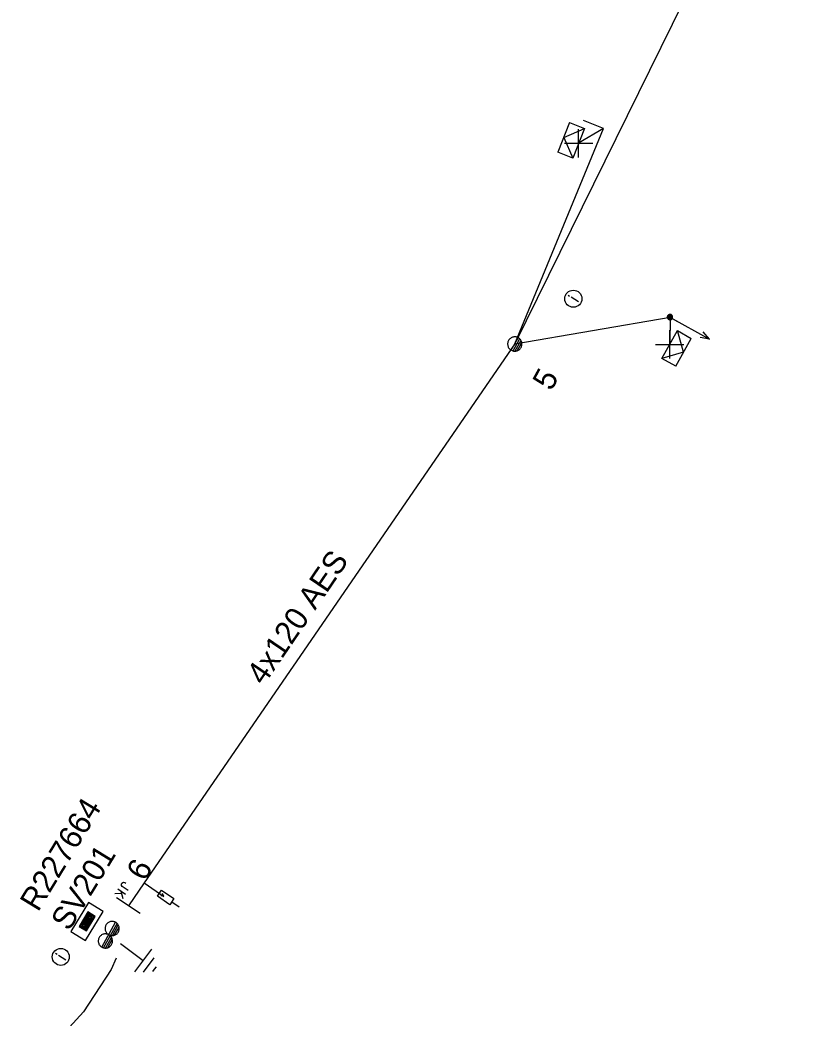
# Model space of a CAD drawing. Extents: x -544780 to -541582, y -1198995 to -1196551.
# Drawn here: x -543891.68 to -543856.56, y -1197432.33 to -1197388.43 of the extents above; entities that cross this region are included whole.
import ezdxf

# ---------------------------------------------------------------- set-up
doc = ezdxf.new("R2010")
doc.units = 0
for name, color, linetype in [('Vrstva 1', 7, 'Continuous'), ('Vrstva 10', 7, 'Continuous'), ('Vrstva 13', 7, 'Continuous'), ('Vrstva 14', 7, 'Continuous'), ('Vrstva 15', 7, 'Continuous'), ('Vrstva 16', 7, 'Continuous'), ('Vrstva 18', 7, 'Continuous'), ('Vrstva 2', 7, 'Continuous'), ('Vrstva 28', 7, 'Continuous'), ('Vrstva 29', 7, 'Continuous'), ('Vrstva 30', 7, 'Continuous'), ('Vrstva 31', 7, 'Continuous'), ('Vrstva 34', 7, 'Continuous'), ('Vrstva 36', 7, 'Continuous'), ('Vrstva 5', 7, 'Continuous'), ('Vrstva 50', 7, 'Continuous'), ('Vrstva 51', 7, 'Continuous'), ('Vrstva 54', 7, 'Continuous'), ('Vrstva 8', 7, 'Continuous'), ('Vrstva 9', 7, 'Continuous')]:
    doc.layers.add(name, color=color, linetype=linetype)

# ---------------------------------------------------------------- blocks, each defined once
blk = doc.blocks.new('NN440')
at = {"layer": 'Vrstva 2'}
for points in [[(0.631, -0.004), (0.627, 0.062), (0.617, 0.127), (0.6, 0.191), (0.577, 0.252), (0.547, 0.311), (0.511, 0.366), (0.469, 0.417), (0.423, 0.464), (0.371, 0.505), (0.316, 0.542), (0.257, 0.571), (0.196, 0.595), (0.132, 0.612), (0.067, 0.622), (0.001, 0.626), (-0.065, 0.622), (-0.13, 0.612), (-0.194, 0.595), (-0.255, 0.571), (-0.314, 0.542), (-0.369, 0.505), (-0.42, 0.464), (-0.467, 0.417), (-0.509, 0.366), (-0.544, 0.311), (-0.574, 0.252), (-0.598, 0.191), (-0.615, 0.127), (-0.626, 0.062), (-0.629, -0.004), (-0.626, -0.07), (-0.615, -0.135), (-0.598, -0.199), (-0.574, -0.26), (-0.544, -0.319), (-0.509, -0.374), (-0.467, -0.426), (-0.42, -0.472), (-0.369, -0.514), (-0.314, -0.55), (-0.255, -0.58), (-0.194, -0.603), (-0.13, -0.62), (-0.065, -0.631), (0.001, -0.634), (0.067, -0.631), (0.132, -0.62), (0.196, -0.603), (0.257, -0.58), (0.316, -0.55), (0.371, -0.514), (0.423, -0.472), (0.469, -0.426), (0.511, -0.374), (0.547, -0.319), (0.577, -0.26), (0.6, -0.199), (0.617, -0.135), (0.627, -0.07), (0.631, -0.004)], [(-0.631, 0), (0.629, 0)], [(-0.601, -0.177), (0.57, -0.177)], [(-0.513, -0.325), (0.501, -0.325)], [(-0.375, -0.473), (0.353, -0.473)]]:
    blk.add_lwpolyline(points, dxfattribs=at)
blk = doc.blocks.new('NN450')
at = {"layer": 'Vrstva 2'}
for points in [[(0, 0), (-0.003, 0.065), (-0.013, 0.13), (-0.031, 0.193), (-0.054, 0.254), (-0.084, 0.312), (-0.119, 0.367), (-0.161, 0.418), (-0.207, 0.464), (-0.258, 0.505), (-0.313, 0.541), (-0.371, 0.571), (-0.432, 0.594), (-0.495, 0.611), (-0.559, 0.621), (-0.625, 0.625), (-0.69, 0.621), (-0.755, 0.611), (-0.818, 0.594), (-0.879, 0.571), (-0.938, 0.541), (-0.992, 0.505), (-1.043, 0.464), (-1.089, 0.418), (-1.13, 0.367), (-1.166, 0.312), (-1.196, 0.254), (-1.219, 0.193), (-1.236, 0.13), (-1.246, 0.065), (-1.25, 0), (-1.246, -0.066), (-1.236, -0.13), (-1.219, -0.193), (-1.196, -0.255), (-1.166, -0.313), (-1.13, -0.368), (-1.089, -0.419), (-1.043, -0.465), (-0.992, -0.506), (-0.937, -0.542), (-0.879, -0.571), (-0.818, -0.595), (-0.755, -0.612), (-0.69, -0.622), (-0.625, -0.625), (-0.559, -0.622), (-0.495, -0.612), (-0.432, -0.595), (-0.37, -0.571), (-0.312, -0.542), (-0.258, -0.506), (-0.207, -0.465), (-0.161, -0.419), (-0.119, -0.368), (-0.084, -0.313), (-0.054, -0.254), (-0.031, -0.193), (-0.013, -0.13), (-0.003, -0.066), (0, 0)], [(1.25, 0), (1.247, 0.065), (1.237, 0.13), (1.219, 0.193), (1.196, 0.254), (1.166, 0.312), (1.131, 0.367), (1.089, 0.418), (1.043, 0.464), (0.992, 0.505), (0.937, 0.541), (0.879, 0.571), (0.818, 0.594), (0.755, 0.611), (0.691, 0.621), (0.625, 0.625), (0.56, 0.621), (0.495, 0.611), (0.432, 0.594), (0.371, 0.571), (0.312, 0.541), (0.258, 0.505), (0.207, 0.464), (0.161, 0.418), (0.12, 0.367), (0.084, 0.312), (0.054, 0.254), (0.031, 0.193), (0.014, 0.13), (0.004, 0.065), (0, 0), (0.004, -0.066), (0.014, -0.13), (0.031, -0.193), (0.054, -0.255), (0.084, -0.313), (0.12, -0.368), (0.161, -0.419), (0.207, -0.465), (0.258, -0.506), (0.313, -0.542), (0.371, -0.571), (0.432, -0.595), (0.495, -0.612), (0.56, -0.622), (0.625, -0.625), (0.691, -0.622), (0.755, -0.612), (0.818, -0.595), (0.88, -0.571), (0.938, -0.542), (0.992, -0.506), (1.043, -0.465), (1.089, -0.419), (1.131, -0.368), (1.166, -0.313), (1.196, -0.254), (1.219, -0.193), (1.237, -0.13), (1.247, -0.066), (1.25, 0)], [(-1.25, 0), (1.25, 0)], [(-1.23, -0.158), (-0.02, -0.158)], [(-1.161, -0.315), (-0.088, -0.315)], [(-1.033, -0.473), (-0.216, -0.473)], [(0.02, -0.158), (1.23, -0.158)], [(0.089, -0.315), (1.162, -0.315)], [(0.217, -0.473), (1.034, -0.473)]]:
    blk.add_lwpolyline(points, dxfattribs=at)
blk = doc.blocks.new('NN560')
at = {"layer": 'Vrstva 2'}
for points in [[(1.999, -0.001), (1.59, 0.141)], [(0, -0.001), (1.999, -0.001)], [(1.999, -0.001), (1.59, -0.134)]]:
    blk.add_lwpolyline(points, dxfattribs=at)
blk = doc.blocks.new('NN840')
at = {"layer": 'Vrstva 15'}
for points in [[(0.003, 0.619), (0.003, -0.631)], [(-0.538, -0.385), (-0.538, -0.71)], [(-0.332, -0.385), (-0.332, -0.798)], [(-0.332, -0.641), (-0.125, -0.385)], [(-0.745, -0.71), (-0.745, -0.66)], [(-0.73, -0.764), (-0.745, -0.71)], [(-0.657, -0.798), (-0.73, -0.764)], [(-0.627, -0.798), (-0.657, -0.798)], [(-0.558, -0.764), (-0.627, -0.798)], [(-0.538, -0.71), (-0.558, -0.764)], [(-0.263, -0.557), (-0.091, -0.798)]]:
    blk.add_lwpolyline(points, dxfattribs=at)
blk = doc.blocks.new('NN770')
at = {"layer": 'Vrstva 10'}
for p, q in [((0.002, 0.187), (0.002, 0.263)), ((0.002, -0.276), (0.002, 0.111))]:
    blk.add_line(p, q, dxfattribs=at)
blk.add_circle((0, -0.008), 0.375, dxfattribs=at)
blk = doc.blocks.new('NN800')
at = {"layer": 'Vrstva 1'}
for points in [[(-0.442, 0.442), (0.442, -0.442)], [(-0.442, -0.442), (0.442, 0.442)]]:
    blk.add_lwpolyline(points, dxfattribs=at)
blk = doc.blocks.new('NN820')
at = {"layer": 'Vrstva 13'}
for points in [[(-0.003, 0.004), (-0.003, -1.049)], [(-0.165, -0.813), (0.165, -0.813)], [(-0.165, -1.473), (-0.165, -0.813)], [(0.165, -0.813), (0.165, -1.473)], [(-0.003, -1.049), (-0.062, -0.926)], [(-0.003, -1.049), (0.057, -0.926)], [(0.165, -1.473), (-0.165, -1.473)], [(-0.003, -1.473), (-0.003, -1.871)]]:
    blk.add_lwpolyline(points, dxfattribs=at)
blk = doc.blocks.new('NN620')
at = {"layer": 'Vrstva 8'}
for points in [[(0.752, 0.004), (-0.748, 0.004)], [(-0.748, 0.004), (-0.748, -0.746)], [(0.752, -0.746), (0.752, 0.004)], [(0.368, -0.18), (-0.376, -0.18)], [(-0.376, -0.18), (-0.376, -0.558)], [(0.321, -0.227), (-0.329, -0.227)], [(-0.329, -0.227), (-0.329, -0.51)], [(0.274, -0.274), (-0.281, -0.274)], [(-0.281, -0.274), (-0.281, -0.463)], [(0.227, -0.321), (-0.234, -0.321)], [(-0.234, -0.321), (-0.234, -0.416)], [(-0.234, -0.416), (0.227, -0.416)], [(-0.193, -0.369), (0.185, -0.369)], [(0.227, -0.416), (0.227, -0.321)], [(0.274, -0.463), (0.274, -0.274)], [(0.321, -0.51), (0.321, -0.227)], [(0.368, -0.558), (0.368, -0.18)], [(-0.748, -0.746), (0.752, -0.746)], [(-0.376, -0.558), (0.368, -0.558)], [(-0.329, -0.51), (0.321, -0.51)], [(-0.281, -0.463), (0.274, -0.463)]]:
    blk.add_lwpolyline(points, dxfattribs=at)
blk = doc.blocks.new('NN630')
at = {"layer": 'Vrstva 9'}
for points in [[(-0.003, -0.7), (-0.703, 0)], [(-0.703, -0.7), (-0.703, 0), (0.697, 0), (0.697, -0.7)], [(-0.003, -0.7), (0.697, 0)], [(-0.703, -0.7), (0.697, -0.7)]]:
    blk.add_lwpolyline(points, dxfattribs=at)
blk = doc.blocks.new('NN810')
at = {"layer": 'Vrstva 14'}
for points in [[(0.004, -0.64), (0.004, -1.89)], [(0.629, -1.89), (-0.621, -1.89)], [(0.388, -2.2), (-0.399, -2.2)], [(0.004, -2.515), (-0.124, -2.515)], [(0.137, -2.515), (0.004, -2.515)]]:
    blk.add_lwpolyline(points, dxfattribs=at)
blk = doc.blocks.new('NN500')
at = {"layer": 'Vrstva 2'}
for points in [[(-0.001, -0.235), (0.023, -0.234), (0.048, -0.23), (0.071, -0.224), (0.094, -0.215), (0.116, -0.204), (0.137, -0.191), (0.156, -0.175), (0.173, -0.158), (0.189, -0.139), (0.202, -0.118), (0.213, -0.096), (0.222, -0.073), (0.229, -0.049), (0.232, -0.025), (0.234, 0), (0.232, 0.024), (0.229, 0.048), (0.222, 0.072), (0.213, 0.095), (0.202, 0.117), (0.189, 0.138), (0.173, 0.157), (0.156, 0.174), (0.137, 0.19), (0.116, 0.203), (0.094, 0.214), (0.071, 0.223), (0.048, 0.229), (0.023, 0.233), (-0.001, 0.235), (-0.026, 0.233), (-0.05, 0.229), (-0.074, 0.223), (-0.097, 0.214), (-0.119, 0.203), (-0.139, 0.19), (-0.158, 0.174), (-0.176, 0.157), (-0.191, 0.138), (-0.205, 0.117), (-0.216, 0.095), (-0.225, 0.072), (-0.231, 0.048), (-0.235, 0.024), (-0.236, 0), (-0.235, -0.025), (-0.231, -0.049), (-0.225, -0.073), (-0.216, -0.096), (-0.205, -0.118), (-0.191, -0.139), (-0.176, -0.158), (-0.158, -0.175), (-0.139, -0.191), (-0.119, -0.204), (-0.097, -0.215), (-0.074, -0.224), (-0.05, -0.23), (-0.026, -0.234), (-0.001, -0.235)], [(-0.001, -0.235), (0.023, -0.234), (0.048, -0.23), (0.071, -0.224), (0.094, -0.215), (0.116, -0.204), (0.137, -0.191), (0.156, -0.175), (0.173, -0.158), (0.189, -0.139), (0.202, -0.118), (0.213, -0.096), (0.222, -0.073), (0.229, -0.049), (0.232, -0.025), (0.234, 0), (0.232, 0.024), (0.229, 0.048), (0.222, 0.072), (0.213, 0.095), (0.202, 0.117), (0.189, 0.138), (0.173, 0.157), (0.156, 0.174), (0.137, 0.19), (0.116, 0.203), (0.094, 0.214), (0.071, 0.223), (0.048, 0.229), (0.023, 0.233), (-0.001, 0.235), (-0.026, 0.233), (-0.05, 0.229), (-0.074, 0.223), (-0.097, 0.214), (-0.119, 0.203), (-0.139, 0.19), (-0.158, 0.174), (-0.176, 0.157), (-0.191, 0.138), (-0.205, 0.117), (-0.216, 0.095), (-0.225, 0.072), (-0.231, 0.048), (-0.235, 0.024), (-0.236, 0), (-0.235, -0.025), (-0.231, -0.049), (-0.225, -0.073), (-0.216, -0.096), (-0.205, -0.118), (-0.191, -0.139), (-0.176, -0.158), (-0.158, -0.175), (-0.139, -0.191), (-0.119, -0.204), (-0.097, -0.215), (-0.074, -0.224), (-0.05, -0.23), (-0.026, -0.234), (-0.001, -0.235)], [(-0.001, -0.206), (0.02, -0.205), (0.041, -0.201), (0.062, -0.196), (0.082, -0.188), (0.101, -0.178), (0.12, -0.167), (0.136, -0.153), (0.151, -0.138), (0.165, -0.121), (0.177, -0.103), (0.186, -0.084), (0.194, -0.064), (0.2, -0.043), (0.203, -0.022), (0.204, 0), (0.203, 0.021), (0.2, 0.042), (0.194, 0.063), (0.186, 0.083), (0.177, 0.102), (0.165, 0.12), (0.151, 0.137), (0.136, 0.152), (0.12, 0.166), (0.101, 0.177), (0.082, 0.187), (0.062, 0.195), (0.041, 0.2), (0.02, 0.204), (-0.001, 0.205), (-0.023, 0.204), (-0.044, 0.2), (-0.065, 0.195), (-0.085, 0.187), (-0.104, 0.177), (-0.122, 0.166), (-0.139, 0.152), (-0.154, 0.137), (-0.167, 0.12), (-0.179, 0.102), (-0.189, 0.083), (-0.197, 0.063), (-0.202, 0.042), (-0.205, 0.021), (-0.207, 0), (-0.205, -0.022), (-0.202, -0.043), (-0.197, -0.064), (-0.189, -0.084), (-0.179, -0.103), (-0.167, -0.121), (-0.154, -0.138), (-0.139, -0.153), (-0.122, -0.167), (-0.104, -0.178), (-0.085, -0.188), (-0.065, -0.196), (-0.044, -0.201), (-0.023, -0.205), (-0.001, -0.206)], [(-0.001, -0.176), (0.017, -0.175), (0.035, -0.172), (0.053, -0.168), (0.07, -0.161), (0.087, -0.153), (0.102, -0.143), (0.116, -0.131), (0.129, -0.118), (0.141, -0.104), (0.151, -0.088), (0.159, -0.072), (0.166, -0.055), (0.171, -0.037), (0.174, -0.019), (0.175, 0), (0.174, 0.018), (0.171, 0.036), (0.166, 0.054), (0.159, 0.071), (0.151, 0.087), (0.141, 0.103), (0.129, 0.117), (0.116, 0.13), (0.102, 0.142), (0.087, 0.152), (0.07, 0.16), (0.053, 0.167), (0.035, 0.172), (0.017, 0.174), (-0.001, 0.175), (-0.02, 0.174), (-0.038, 0.172), (-0.056, 0.167), (-0.073, 0.16), (-0.089, 0.152), (-0.105, 0.142), (-0.119, 0.13), (-0.132, 0.117), (-0.143, 0.103), (-0.153, 0.087), (-0.162, 0.071), (-0.168, 0.054), (-0.173, 0.036), (-0.176, 0.018), (-0.177, 0), (-0.176, -0.019), (-0.173, -0.037), (-0.168, -0.055), (-0.162, -0.072), (-0.153, -0.088), (-0.143, -0.104), (-0.132, -0.118), (-0.119, -0.131), (-0.105, -0.143), (-0.089, -0.153), (-0.073, -0.161), (-0.056, -0.168), (-0.038, -0.172), (-0.02, -0.175), (-0.001, -0.176)], [(-0.001, -0.147), (0.014, -0.146), (0.029, -0.143), (0.044, -0.139), (0.058, -0.134), (0.072, -0.127), (0.085, -0.119), (0.097, -0.109), (0.107, -0.098), (0.117, -0.086), (0.125, -0.073), (0.132, -0.06), (0.138, -0.046), (0.142, -0.031), (0.144, -0.016), (0.145, 0), (0.144, 0.015), (0.142, 0.03), (0.138, 0.045), (0.132, 0.059), (0.125, 0.073), (0.117, 0.086), (0.107, 0.097), (0.097, 0.108), (0.085, 0.118), (0.072, 0.126), (0.058, 0.133), (0.044, 0.139), (0.029, 0.143), (0.014, 0.145), (-0.001, 0.146), (-0.017, 0.145), (-0.032, 0.143), (-0.046, 0.139), (-0.061, 0.133), (-0.074, 0.126), (-0.087, 0.118), (-0.099, 0.108), (-0.11, 0.097), (-0.119, 0.086), (-0.128, 0.073), (-0.135, 0.059), (-0.14, 0.045), (-0.144, 0.03), (-0.147, 0.015), (-0.147, 0), (-0.147, -0.016), (-0.144, -0.031), (-0.14, -0.046), (-0.135, -0.06), (-0.128, -0.073), (-0.119, -0.086), (-0.11, -0.098), (-0.099, -0.109), (-0.087, -0.119), (-0.074, -0.127), (-0.061, -0.134), (-0.046, -0.139), (-0.032, -0.143), (-0.017, -0.146), (-0.001, -0.147)], [(-0.001, -0.117), (0.011, -0.116), (0.023, -0.114), (0.035, -0.111), (0.046, -0.107), (0.057, -0.101), (0.067, -0.095), (0.077, -0.087), (0.085, -0.078), (0.093, -0.069), (0.1, -0.059), (0.105, -0.048), (0.11, -0.036), (0.113, -0.025), (0.115, -0.013), (0.115, 0), (0.115, 0.012), (0.113, 0.024), (0.11, 0.036), (0.105, 0.047), (0.1, 0.058), (0.093, 0.068), (0.085, 0.078), (0.077, 0.086), (0.067, 0.094), (0.057, 0.101), (0.046, 0.106), (0.035, 0.11), (0.023, 0.114), (0.011, 0.116), (-0.001, 0.116), (-0.013, 0.116), (-0.025, 0.114), (-0.037, 0.11), (-0.049, 0.106), (-0.059, 0.101), (-0.07, 0.094), (-0.079, 0.086), (-0.088, 0.078), (-0.096, 0.068), (-0.102, 0.058), (-0.108, 0.047), (-0.112, 0.036), (-0.115, 0.024), (-0.117, 0.012), (-0.118, 0), (-0.117, -0.013), (-0.115, -0.025), (-0.112, -0.036), (-0.108, -0.048), (-0.102, -0.059), (-0.096, -0.069), (-0.088, -0.078), (-0.079, -0.087), (-0.07, -0.095), (-0.059, -0.101), (-0.049, -0.107), (-0.037, -0.111), (-0.025, -0.114), (-0.013, -0.116), (-0.001, -0.117)], [(-0.001, -0.087), (0.008, -0.087), (0.017, -0.085), (0.026, -0.083), (0.034, -0.08), (0.042, -0.076), (0.05, -0.071), (0.057, -0.065), (0.063, -0.059), (0.069, -0.051), (0.074, -0.044), (0.078, -0.036), (0.081, -0.027), (0.084, -0.019), (0.085, -0.01), (0.086, 0), (0.085, 0.009), (0.084, 0.018), (0.081, 0.026), (0.078, 0.035), (0.074, 0.043), (0.069, 0.051), (0.063, 0.058), (0.057, 0.064), (0.05, 0.07), (0.042, 0.075), (0.034, 0.079), (0.026, 0.082), (0.017, 0.085), (0.008, 0.086), (-0.001, 0.087), (-0.01, 0.086), (-0.019, 0.085), (-0.028, 0.082), (-0.037, 0.079), (-0.045, 0.075), (-0.052, 0.07), (-0.059, 0.064), (-0.066, 0.058), (-0.072, 0.051), (-0.077, 0.043), (-0.081, 0.035), (-0.084, 0.026), (-0.086, 0.018), (-0.088, 0.009), (-0.088, 0), (-0.088, -0.01), (-0.086, -0.019), (-0.084, -0.027), (-0.081, -0.036), (-0.077, -0.044), (-0.072, -0.052), (-0.066, -0.059), (-0.059, -0.065), (-0.052, -0.071), (-0.045, -0.076), (-0.037, -0.08), (-0.028, -0.083), (-0.019, -0.085), (-0.01, -0.087), (-0.001, -0.087)], [(-0.001, -0.058), (0.005, -0.057), (0.011, -0.056), (0.016, -0.055), (0.022, -0.053), (0.027, -0.05), (0.032, -0.047), (0.037, -0.043), (0.041, -0.039), (0.045, -0.034), (0.048, -0.029), (0.051, -0.024), (0.053, -0.018), (0.055, -0.012), (0.056, -0.006), (0.056, 0), (0.056, 0.006), (0.055, 0.011), (0.053, 0.017), (0.051, 0.023), (0.048, 0.028), (0.045, 0.033), (0.041, 0.038), (0.037, 0.042), (0.032, 0.046), (0.027, 0.049), (0.022, 0.052), (0.016, 0.054), (0.011, 0.056), (0.005, 0.057), (-0.001, 0.057), (-0.007, 0.057), (-0.013, 0.056), (-0.019, 0.054), (-0.025, 0.052), (-0.03, 0.049), (-0.035, 0.046), (-0.04, 0.042), (-0.044, 0.038), (-0.048, 0.033), (-0.051, 0.028), (-0.054, 0.023), (-0.056, 0.017), (-0.057, 0.011), (-0.058, 0.006), (-0.059, 0), (-0.058, -0.006), (-0.057, -0.012), (-0.056, -0.018), (-0.054, -0.024), (-0.051, -0.029), (-0.048, -0.034), (-0.044, -0.039), (-0.04, -0.043), (-0.035, -0.047), (-0.03, -0.05), (-0.025, -0.053), (-0.019, -0.055), (-0.013, -0.056), (-0.007, -0.057), (-0.001, -0.058)], [(-0.001, -0.028), (0.002, -0.028), (0.005, -0.028), (0.007, -0.027), (0.01, -0.026), (0.013, -0.024), (0.015, -0.023), (0.017, -0.021), (0.019, -0.019), (0.021, -0.017), (0.023, -0.014), (0.024, -0.012), (0.025, -0.009), (0.026, -0.006), (0.026, -0.003), (0.027, 0), (0.026, 0.002), (0.026, 0.005), (0.025, 0.008), (0.024, 0.011), (0.023, 0.013), (0.021, 0.016), (0.019, 0.018), (0.017, 0.02), (0.015, 0.022), (0.013, 0.024), (0.01, 0.025), (0.007, 0.026), (0.005, 0.027), (0.002, 0.027), (-0.001, 0.027), (-0.004, 0.027), (-0.007, 0.027), (-0.01, 0.026), (-0.012, 0.025), (-0.015, 0.024), (-0.018, 0.022), (-0.02, 0.02), (-0.022, 0.018), (-0.024, 0.016), (-0.025, 0.013), (-0.027, 0.011), (-0.028, 0.008), (-0.028, 0.005), (-0.029, 0.002), (-0.029, 0), (-0.029, -0.003), (-0.028, -0.006), (-0.028, -0.009), (-0.027, -0.012), (-0.025, -0.014), (-0.024, -0.017), (-0.022, -0.019), (-0.02, -0.021), (-0.018, -0.023), (-0.015, -0.024), (-0.012, -0.026), (-0.01, -0.027), (-0.007, -0.028), (-0.004, -0.028), (-0.001, -0.028)], [(0.234, 0), (0.704, 0)]]:
    blk.add_lwpolyline(points, dxfattribs=at)
blk = doc.blocks.new('NN510')
at = {"layer": 'Vrstva 2'}
blk.add_lwpolyline([(0.001, 0.002), (0.001, 0.939)], dxfattribs=at)

msp = doc.modelspace()

# ---------------------------------------------------------------- linework, layer by layer
at = {"layer": 'Vrstva 5'}
msp.add_lwpolyline([(-543887.452, -1197429.695), (-543887.67, -1197430.2), (-543888.89, -1197432.05), (-543890.9, -1197434.26)], dxfattribs=at)
at = {"layer": 'Vrstva 50'}
msp.add_lwpolyline([(-543856.56, -1197375.58), (-543869.91, -1197402.679), (-543886.21, -1197426.379), (-543886.903, -1197427.387)], dxfattribs=at)
at = {"layer": 'Vrstva 54'}
msp.add_lwpolyline([(-543869.91, -1197402.679), (-543866.007, -1197393.197), (-543867.1, -1197393.851)], dxfattribs=at)
at = {"layer": 'Vrstva 8'}
msp.add_lwpolyline([(-543869.91, -1197402.679), (-543863.075, -1197401.496), (-543863.089, -1197402.696)], dxfattribs=at)

# ---------------------------------------------------------------- block references
at = {"layer": 'Vrstva 13'}
for name, p, rotation in [('NN510', (-543866.006, -1197393.197), 68.39272227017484), ('NN560', (-543863.075, -1197401.496), -29.260191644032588)]:
    msp.add_blockref(name, p, dxfattribs=dict(at, rotation=rotation))
for name, p, xscale, yscale, rotation in [('NN500', (-543863.075, -1197401.496), 0.5000000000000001, 0.4999999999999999, -29.25999985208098), ('NN440', (-543869.909, -1197402.68), 0.4999999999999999, 0.5000000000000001, 61.47566946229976), ('NN450', (-543887.774, -1197428.666), 0.5, 0.5, 61.475669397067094)]:
    msp.add_blockref(name, p, dxfattribs=dict(at, xscale=xscale, yscale=yscale, rotation=rotation))
at = {"layer": 'Vrstva 15', "rotation": 52.80014439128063}
msp.add_blockref('NN810', (-543887.774, -1197428.665), dxfattribs=at)
at = {"layer": 'Vrstva 16', "rotation": 55.48163610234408}
msp.add_blockref('NN820', (-543886.21, -1197426.379), dxfattribs=at)
at = {"layer": 'Vrstva 18', "rotation": -124.25060284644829}
msp.add_blockref('NN840', (-543886.903, -1197427.387), dxfattribs=at)
at = {"layer": 'Vrstva 28', "rotation": -121.34299999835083}
msp.add_blockref('NN620', (-543888.414, -1197428.275), dxfattribs=at)
at = {"layer": 'Vrstva 31'}
for p, rotation in [((-543867.1, -1197393.851), -111.60727778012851), ((-543863.089, -1197402.697), 60.7411277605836)]:
    msp.add_blockref('NN630', p, dxfattribs=dict(at, rotation=rotation))
at = {"layer": 'Vrstva 34', "rotation": 45}
for p in [(-543867.1, -1197393.85), (-543863.089, -1197402.696)]:
    msp.add_blockref('NN800', p, dxfattribs=at)
at = {"layer": 'Vrstva 36'}
for p, rotation in [((-543867.336, -1197400.683), 58.516302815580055), ((-543889.892, -1197429.636), 58.51630274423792)]:
    msp.add_blockref('NN770', p, dxfattribs=dict(at, rotation=rotation))

# ---------------------------------------------------------------- texts
at = {"layer": 'Vrstva 14'}
for s, p in [('5', (-543868.298, -1197404.784)), ('6', (-543886.167, -1197426.352))]:
    msp.add_text(s, height=1, rotation=61.476, dxfattribs=at).set_placement(p)
at = {"layer": 'Vrstva 29'}
msp.add_text('R227664', height=1, rotation=58.657, dxfattribs=at).set_placement((-543890.885, -1197427.697))
at = {"layer": 'Vrstva 30'}
msp.add_text('SV201', height=1, rotation=58.516, dxfattribs=at).set_placement((-543889.523, -1197428.544))
at = {"layer": 'Vrstva 51'}
msp.add_text('4x120 AES', height=1, rotation=55.749, dxfattribs=at).set_placement((-543880.954, -1197417.736))

doc.saveas('drawing.dxf')
